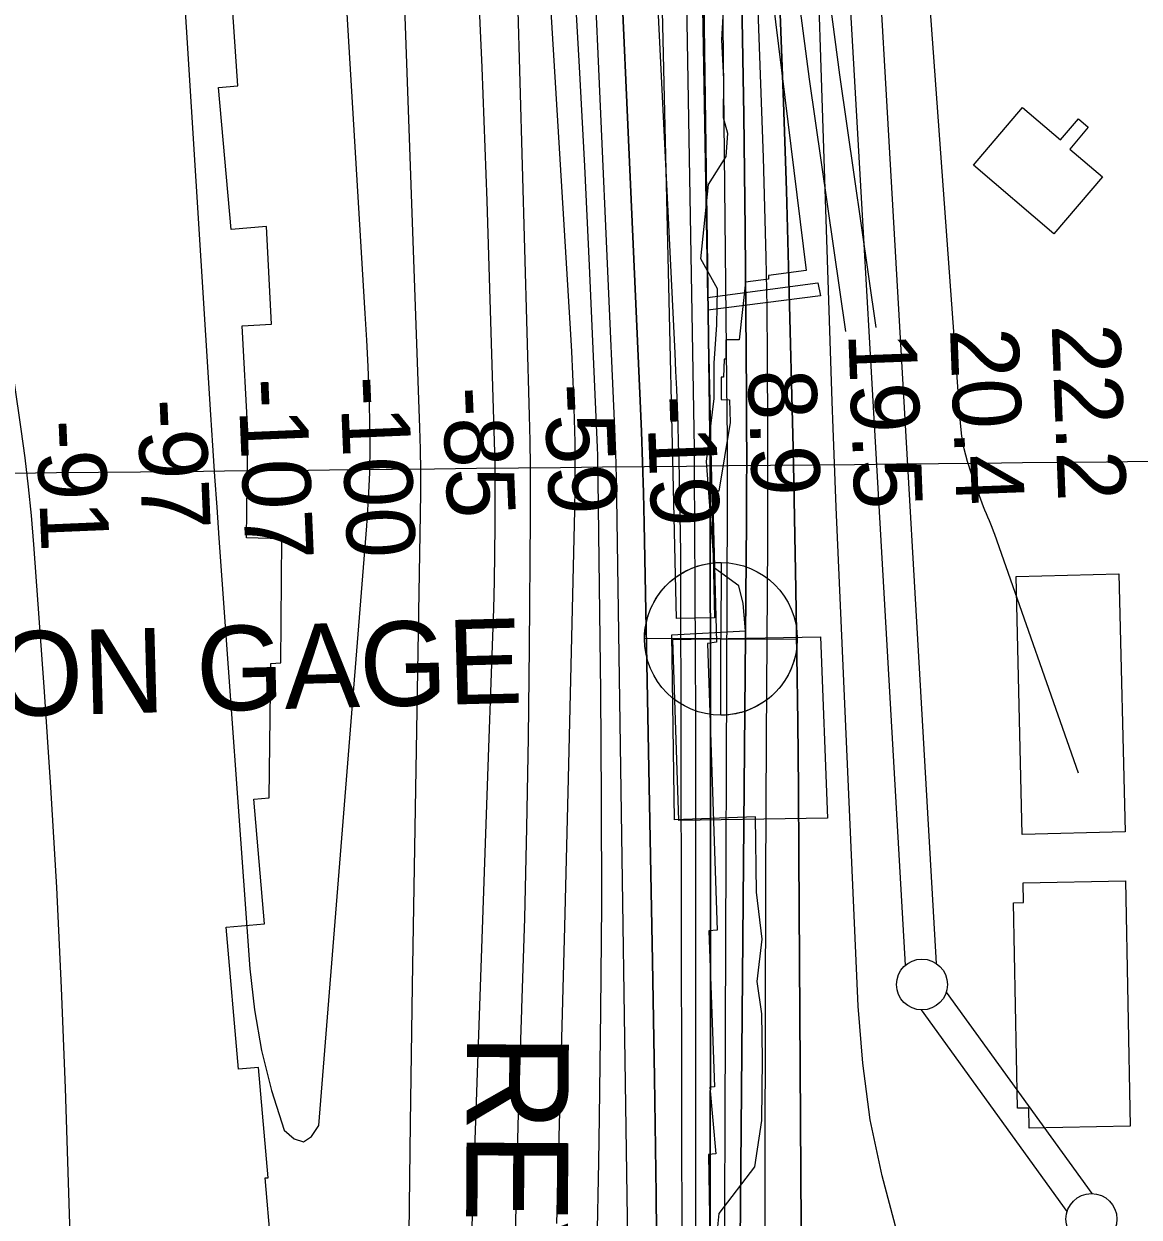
# Model space of a CAD drawing. Extents: x 3651524 to 3689615, y 505651 to 531377.
# Drawn here: x 3659567 to 3660662, y 522494 to 523666 of the extents above; entities that cross this region are included whole.
import ezdxf

# ---------------------------------------------------------------- set-up
doc = ezdxf.new("R2010")
doc.units = 0
for name, color, linetype in [('V-BLDG-OTLN', 7, 'Continuous'), ('V-CHAN-DOCK', 7, 'Continuous'), ('V-GRID-MAJR', 7, 'Continuous'), ('V-RIVR-EDGE', 7, 'Continuous'), ('V-RIVR-GAGE', 7, 'Continuous'), ('V-RIVR-GAGE-IDEN', 7, 'Continuous'), ('V-RIVR-RANG', 7, 'Continuous'), ('V-ROAD-CNTR', 7, 'Continuous'), ('V-RRAP-RVMT', 7, 'Continuous'), ('V-RRAP-RVMT-IDEN', 7, 'Continuous'), ('V-SURV-LINE', 7, 'Continuous'), ('V-TOPO-DPTH', 7, 'Continuous'), ('V-TOPO-MAJR', 7, 'Continuous'), ('V-TOPO-MINR', 7, 'Continuous'), ('V-TOPO-WATR', 7, 'Continuous')]:
    doc.layers.add(name, color=color, linetype=linetype)

msp = doc.modelspace()

# ---------------------------------------------------------------- linework, layer by layer
at = {"layer": 'V-BLDG-OTLN'}
for points in [[(3660499.185, 523526.95), (3660547.415, 523583.372), (3660584.617, 523551.569), (3660602.316, 523572.272), (3660612.052, 523563.947), (3660593.831, 523542.631), (3660625.819, 523515.286), (3660578.107, 523459.481)], [(3660547.2, 522869.505), (3660541.05, 523122.922), (3660642.023, 523125.374), (3660648.173, 522871.956)], [(3660648.548, 522824.021), (3660653.145, 522583.031), (3660553.914, 522581.134), (3660553.539, 522600.857), (3660542.416, 522600.646), (3660538.564, 522802.521), (3660548.349, 522802.707), (3660547.981, 522822.102)]]:
    msp.add_lwpolyline(points, close=True, dxfattribs=at)
at = {"layer": 'V-CHAN-DOCK'}
for points in [[(3660349.073, 523398.565), (3660238.38, 523384.489), (3660244.914, 523082.139), (3660207.497, 523081.612), (3660186.068, 524019.57), (3660225.288, 524021.251), (3660228.491, 523900.065), (3660307.638, 523909.948), (3660308.615, 523898.056), (3660229.488, 523889.36), (3660238.008, 523396.965), (3660346.324, 523411.082), (3660349.073, 523398.565)], [(3660356.036, 522885.416), (3660209.928, 522883.247), (3660204.16, 523060.891), (3660349.091, 523063.674), (3660356.036, 522885.416)]]:
    msp.add_lwpolyline(points, dxfattribs=at)
at = {"layer": 'V-GRID-MAJR'}
msp.add_spline([(3655639.78, 523183.706), (3660918.553, 523238.605), (3666197.317, 523294.271), (3671476.073, 523350.705), (3676754.821, 523407.907), (3682033.561, 523465.877), (3687312.292, 523524.615)], degree=3, dxfattribs=at)
at = {"layer": 'V-RIVR-EDGE'}
msp.add_lwpolyline([(3660246.867, 522470.971), (3660249.383, 522497.312), (3660284.422, 522543.18), (3660291.274, 522588.505), (3660292.037, 522649.163), (3660291.533, 522693.28), (3660286.71, 522725.154), (3660291.715, 522766.807), (3660286.314, 522812.775), (3660285.272, 522886.918), (3660205.611, 522884.051), (3660202.996, 523065.425), (3660275.307, 523069.535), (3660272.923, 523096.501), (3660268.677, 523113.668), (3660244.823, 523130.883), (3660237.116, 523235.678), (3660244.622, 523297.545), (3660244.709, 523332.47), (3660247.252, 523369.841), (3660247.952, 523405.377), (3660231.482, 523434.829), (3660239.015, 523507.724), (3660256.239, 523535.255), (3660258.133, 523557.921), (3660253.882, 523573.25), (3660253.976, 523611.238), (3660252.233, 523649.844), (3660254.156, 523684.152)], dxfattribs=at)
at = {"layer": 'V-RIVR-GAGE'}
for points in [[(3660251.372, 523136.632), (3660251.187, 523061.632), (3660176.187, 523061.817), (3660176.222, 523063.921), (3660176.344, 523066.494), (3660176.599, 523069.484), (3660176.97, 523072.441), (3660177.426, 523075.21), (3660178.036, 523078.188), (3660178.669, 523080.767), (3660179.337, 523083.139), (3660180.102, 523085.546), (3660181.078, 523088.277), (3660182.015, 523090.62), (3660183.026, 523092.922), (3660184.228, 523095.418), (3660185.664, 523098.124), (3660187.016, 523100.454), (3660188.419, 523102.683), (3660190.831, 523106.152), (3660192.531, 523108.37), (3660194.759, 523111.037), (3660196.909, 523113.39), (3660198.751, 523115.255), (3660201.525, 523117.834), (3660203.868, 523119.821), (3660206.33, 523121.739), (3660209.448, 523123.943), (3660211.827, 523125.474), (3660214.418, 523127.001), (3660217.397, 523128.59), (3660220.038, 523129.858), (3660222.632, 523130.984), (3660226.267, 523132.371), (3660229.51, 523133.432), (3660232.686, 523134.315), (3660235.942, 523135.066), (3660239.344, 523135.691), (3660243.397, 523136.226), (3660246.387, 523136.478), (3660248.933, 523136.598)], [(3660251.001, 522986.632), (3660251.187, 523061.632), (3660326.186, 523061.446), (3660326.133, 523058.791), (3660325.946, 523055.632), (3660325.694, 523053.041), (3660325.346, 523050.438), (3660324.808, 523047.313), (3660324.16, 523044.315), (3660323.292, 523040.996), (3660322.644, 523038.852), (3660321.671, 523036), (3660320.542, 523033.088), (3660319.442, 523030.547), (3660318.252, 523028.058), (3660316.969, 523025.608), (3660315.622, 523023.251), (3660313.978, 523020.617), (3660312.477, 523018.405), (3660310.353, 523015.541), (3660308.21, 523012.915), (3660305.578, 523009.993), (3660303.282, 523007.678), (3660300.793, 523005.38), (3660298.609, 523003.526), (3660296.966, 523002.224), (3660294.31, 523000.269), (3660292.396, 522998.968), (3660289.876, 522997.381), (3660287.212, 522995.851), (3660284.492, 522994.432), (3660282.368, 522993.421), (3660280.097, 522992.428), (3660277.48, 522991.392), (3660274.769, 522990.435), (3660271.493, 522989.433), (3660268.332, 522988.618), (3660265.902, 522988.089), (3660263.146, 522987.591), (3660260.759, 522987.245), (3660257.97, 522986.939), (3660255.774, 522986.772), (3660253.203, 522986.659)]]:
    msp.add_lwpolyline(points, close=True, dxfattribs=at)
msp.add_circle((3660251.187, 523061.632), 75, dxfattribs=at)
at = {"layer": 'V-ROAD-CNTR'}
for points in [[(3660403.73, 523367.378), (3660368.074, 523615.406), (3660346.877, 523777.012), (3660336.94, 523901.565), (3660333.341, 523955.329), (3660348.907, 524360.899), (3660351.762, 524756.645), (3660356.59, 524937.749), (3660437.61, 525023.281)], [(3660374.001, 523363.346), (3660338.353, 523611.321), (3660317.033, 523773.866), (3660307.02, 523899.37), (3660303.302, 523954.901), (3660314.174, 524238.169)]]:
    msp.add_lwpolyline(points, dxfattribs=at)
at = {"layer": 'V-RRAP-RVMT'}
for p, q in [((3660276.057, 523900.574), (3660334.975, 523423.42)), ((3659776.938, 523604.624), (3659770.445, 523697.82)), ((3659757.953, 523603.024), (3659776.938, 523604.624)), ((3659770.093, 523463.556), (3659757.953, 523603.024)), ((3659804.866, 523466.556), (3659770.093, 523463.556)), ((3659809.762, 523370.661), (3659804.866, 523466.556)), ((3660334.975, 523423.42), (3660297.909, 523418.323)), ((3660275.253, 523411.785), (3660269.018, 523355.39)), ((3660297.986, 523414.735), (3660275.253, 523411.785)), ((3660297.909, 523418.323), (3660297.986, 523414.735)), ((3659780.985, 523369.161), (3659809.762, 523370.661)), ((3659786.457, 523265.619), (3659780.985, 523369.161)), ((3660255.98, 523355.177), (3660255.912, 523336.375)), ((3660269.018, 523355.39), (3660255.98, 523355.177)), ((3660254.322, 523336.189), (3660253.762, 523318.56)), ((3660255.912, 523336.375), (3660254.322, 523336.189)), ((3660251.416, 523318.528), (3660251.393, 523296.645)), ((3660253.762, 523318.56), (3660251.416, 523318.528)), ((3660251.393, 523296.645), (3660259.776, 523296.266)), ((3660259.776, 523296.266), (3660260.158, 523273.981)), ((3660260.158, 523273.981), (3660249.156, 523206.79)), ((3659785.469, 523160.796), (3659786.457, 523265.619)), ((3660249.156, 523206.79), (3660242.94, 523206.6)), ((3660242.94, 523206.6), (3660246.991, 523058.508)), ((3659819.864, 523159.894), (3659785.469, 523160.796)), ((3659819.1, 523038.12), (3659819.864, 523159.894)), ((3660246.991, 523058.508), (3660237.917, 523057.026)), ((3660237.917, 523057.026), (3660247.481, 522775.556)), ((3659807.571, 522905.41), (3659809.257, 523037.468)), ((3659809.257, 523037.468), (3659819.1, 523038.12)), ((3659792.521, 522904.101), (3659807.571, 522905.41)), ((3659803.113, 522781.814), (3659792.521, 522904.101)), ((3659765.245, 522778.414), (3659803.113, 522781.814)), ((3659777.386, 522639.004), (3659765.245, 522778.414)), ((3660247.481, 522775.556), (3660239.319, 522775.047)), ((3660239.319, 522775.047), (3660244.772, 522621.622)), ((3659797.169, 522640.754), (3659777.386, 522639.004)), ((3659806.588, 522532.454), (3659797.169, 522640.754)), ((3660244.772, 522621.622), (3660240.476, 522621.314)), ((3660240.476, 522621.314), (3660246.141, 522555.877)), ((3660246.141, 522555.877), (3660239.124, 522555.264)), ((3660239.124, 522555.264), (3660240.322, 522474.722)), ((3659803.615, 522532.204), (3659806.588, 522532.454)), ((3659814.528, 522406.771), (3659803.615, 522532.204))]:
    msp.add_line(p, q, dxfattribs=at)
at = {"layer": 'V-SURV-LINE'}
for points in [[(3660386.448, 524067.969), (3660462.538, 522742.955)], [(3660432.586, 522741.256), (3660356.496, 524066.27)], [(3660472.563, 522714.753), (3660615.577, 522516.868)], [(3660591.268, 522499.288), (3660448.254, 522697.172)]]:
    msp.add_lwpolyline(points, dxfattribs=at)
for centre in [(3660448.708, 522722.152), (3660615.123, 522491.888)]:
    msp.add_circle(centre, 25, dxfattribs=at)
at = {"layer": 'V-TOPO-DPTH'}
for points in [[(3660211.802, 521616.591), (3660212.444, 521726.88), (3660212.987, 521837.171), (3660213.746, 522016.055), (3660213.815, 522036.903), (3660213.859, 522057.752), (3660213.863, 522078.601), (3660213.842, 522099.449), (3660211.829, 523128.812), (3660211.746, 523146.783), (3660211.599, 523164.754), (3660211.355, 523182.724), (3660211.047, 523200.693), (3660211.032, 523201.451), (3660210.646, 523219.04), (3660210.21, 523236.627), (3660209.699, 523254.213), (3660209.139, 523271.797), (3660208.5, 523289.379), (3660207.808, 523306.958), (3660207.036, 523324.534), (3660206.209, 523342.108), (3660158.102, 524317.479)], [(3660211.802, 521616.591), (3660212.444, 521726.88), (3660212.987, 521837.171), (3660213.746, 522016.055), (3660213.815, 522036.903), (3660213.859, 522057.752), (3660213.863, 522078.601), (3660213.842, 522099.449), (3660211.829, 523128.812), (3660211.746, 523146.783), (3660211.599, 523164.754), (3660211.355, 523182.724), (3660211.047, 523200.693), (3660211.032, 523201.451), (3660210.646, 523219.04), (3660210.21, 523236.627), (3660209.699, 523254.213), (3660209.139, 523271.797), (3660208.5, 523289.379), (3660207.808, 523306.958), (3660207.036, 523324.534), (3660206.209, 523342.108), (3660158.102, 524317.479)], [(3660228.583, 524108.955), (3660240.247, 523264.138), (3660240.404, 523250.988), (3660240.528, 523237.839), (3660240.603, 523224.689), (3660240.645, 523211.539), (3660240.979, 522962.568), (3660241.071, 522824.932), (3660241.041, 522687.297), (3660240.826, 522549.662), (3660240.489, 522412.026), (3660239.595, 522125.275), (3660239.479, 522091.694), (3660239.348, 522058.113), (3660239.195, 522024.533), (3660239.026, 521990.952), (3660236.656, 521547.642)], [(3660236.656, 521547.642), (3660239.026, 521990.952), (3660239.195, 522024.533), (3660239.348, 522058.113), (3660239.479, 522091.694), (3660239.595, 522125.275), (3660240.489, 522412.026), (3660240.826, 522549.662), (3660241.041, 522687.297), (3660241.071, 522824.932), (3660240.979, 522962.568), (3660240.645, 523211.539), (3660240.603, 523224.689), (3660240.528, 523237.839), (3660240.404, 523250.988), (3660240.247, 523264.138), (3660228.583, 524108.955)], [(3660142.159, 523962.069), (3660171.98, 523295.464), (3660173.213, 523265.333), (3660174.294, 523235.198), (3660175.145, 523205.056), (3660175.844, 523174.908), (3660184.165, 522745.258), (3660186.081, 522630.627), (3660187.591, 522515.991), (3660188.492, 522401.349), (3660188.988, 522286.702), (3660189.341, 522074.544), (3660189.347, 522065.974), (3660189.343, 522057.403), (3660189.324, 522048.833), (3660189.294, 522040.262), (3660188.968, 521966.904), (3660188.735, 521921.655), (3660188.457, 521876.406), (3660188.114, 521831.158), (3660187.726, 521785.909), (3660180.444, 521002.622)], [(3660142.159, 523962.069), (3660171.98, 523295.464), (3660173.213, 523265.333), (3660174.294, 523235.198), (3660175.145, 523205.056), (3660175.844, 523174.908), (3660184.165, 522745.258), (3660186.081, 522630.627), (3660187.591, 522515.991), (3660188.492, 522401.349), (3660188.988, 522286.702), (3660189.341, 522074.544), (3660189.347, 522065.974), (3660189.343, 522057.403), (3660189.324, 522048.833), (3660189.294, 522040.262), (3660188.968, 521966.904), (3660188.735, 521921.655), (3660188.457, 521876.406), (3660188.114, 521831.158), (3660187.726, 521785.909), (3660180.444, 521002.622)], [(3660153.012, 521270.884), (3660160.238, 522044.457), (3660160.306, 522050.41), (3660160.388, 522056.363), (3660160.494, 522062.316), (3660160.615, 522068.268), (3660161.2, 522094.568), (3660161.593, 522113.671), (3660161.942, 522132.774), (3660162.227, 522151.879), (3660162.468, 522170.984), (3660162.638, 522186.508), (3660162.828, 522213.376), (3660162.881, 522240.243), (3660162.727, 522267.11), (3660162.434, 522293.977), (3660149.09, 523199.972), (3660148.762, 523217.069), (3660148.334, 523234.164), (3660147.754, 523251.254), (3660147.073, 523268.341), (3660119.703, 523886.484)], [(3660153.012, 521270.884), (3660160.238, 522044.457), (3660160.306, 522050.41), (3660160.388, 522056.363), (3660160.494, 522062.316), (3660160.615, 522068.268), (3660161.2, 522094.568), (3660161.593, 522113.671), (3660161.942, 522132.774), (3660162.227, 522151.879), (3660162.468, 522170.984), (3660162.638, 522186.508), (3660162.828, 522213.376), (3660162.881, 522240.243), (3660162.727, 522267.11), (3660162.434, 522293.977), (3660149.09, 523199.972), (3660148.762, 523217.069), (3660148.334, 523234.164), (3660147.754, 523251.254), (3660147.073, 523268.341), (3660119.703, 523886.484)], [(3660271.866, 523688.051), (3660273.826, 523575.875), (3660275.141, 523463.686), (3660276.339, 523301.804), (3660276.495, 523270.545), (3660276.549, 523239.285), (3660276.452, 523208.025), (3660276.255, 523176.765), (3660267.782, 522208.587), (3660267.561, 522183.572), (3660267.337, 522158.557), (3660267.11, 522133.542), (3660266.879, 522108.527), (3660266.468, 522064.344), (3660266.441, 522061.42), (3660266.416, 522058.497), (3660266.393, 522055.574), (3660266.37, 522052.65), (3660259.75, 521154.194)], [(3660259.75, 521154.194), (3660266.37, 522052.65), (3660266.393, 522055.574), (3660266.416, 522058.497), (3660266.441, 522061.42), (3660266.468, 522064.344), (3660266.879, 522108.527), (3660267.11, 522133.542), (3660267.337, 522158.557), (3660267.561, 522183.572), (3660267.782, 522208.587), (3660276.255, 523176.765), (3660276.452, 523208.025), (3660276.549, 523239.285), (3660276.495, 523270.545), (3660276.339, 523301.804), (3660275.141, 523463.686), (3660273.826, 523575.875), (3660271.866, 523688.051)], [(3660309.51, 523675.548), (3660312.752, 523588.682), (3660315.51, 523501.8), (3660317.944, 523414.906), (3660322.125, 523249.186), (3660322.223, 523245.144), (3660322.315, 523241.102), (3660322.399, 523237.06), (3660322.476, 523233.018), (3660324.702, 523110.507), (3660325.771, 523045.208), (3660326.684, 522979.908), (3660327.361, 522914.604), (3660327.883, 522849.298), (3660332.384, 522121.58), (3660332.507, 522091.306), (3660332.543, 522061.033), (3660332.45, 522030.759), (3660332.271, 522000.486), (3660329.688, 521679.827), (3660328.437, 521562.401)]]:
    msp.add_lwpolyline(points, dxfattribs=at)
at = {"layer": 'V-TOPO-MAJR'}
for points in [[(3659716.655, 523813.725), (3659750.092, 523281.62), (3659752.036, 523251.342), (3659754.034, 523221.068), (3659756.113, 523190.799), (3659758.246, 523160.535), (3659788.634, 522737.546), (3659793.221, 522697.154), (3659799.987, 522657.224), (3659810.021, 522617.987), (3659822.233, 522579.213), (3659832.093, 522570.691), (3659841.212, 522567.695), (3659849.218, 522572.989), (3659856.482, 522583.808), (3659903.523, 523172.762), (3659905.191, 523198.761), (3659906.317, 523224.774), (3659906.631, 523250.811), (3659906.402, 523276.862), (3659905.626, 523302.919), (3659904.666, 523328.968), (3659903.427, 523355.005), (3659902.003, 523381.035), (3659845.319, 524324.679)], [(3660129.686, 522465.554), (3660131.231, 522547.943), (3660132.002, 522591.917), (3660133.374, 522696.297), (3660134.134, 522800.679), (3660133.978, 522905.063), (3660133.21, 523009.449), (3660130.768, 523217.274), (3660130.635, 523225.363), (3660130.45, 523233.45), (3660130.188, 523241.536), (3660129.874, 523249.62), (3660122.084, 523428.422), (3660117.508, 523525.888), (3660112.494, 523623.331), (3660106.824, 523720.737)]]:
    msp.add_lwpolyline(points, dxfattribs=at)
at = {"layer": 'V-TOPO-MINR'}
for points in [[(3660453.124, 522384.898), (3660423.959, 522480.021), (3660409.533, 522534.4), (3660397.915, 522589.264), (3660390.51, 522644.852), (3660385.913, 522700.925), (3660364.544, 523190.816), (3660363.454, 523216.759), (3660362.419, 523242.703), (3660361.468, 523268.651), (3660360.572, 523294.601), (3660336.683, 524020.527), (3660334.835, 524077.811), (3660333.038, 524135.097), (3660331.316, 524192.385), (3660329.644, 524249.674), (3660328.817, 524278.653), (3660327.721, 524321.457), (3660326.792, 524364.263), (3660326.111, 524407.075), (3660325.598, 524449.889), (3660316.37, 525466.02)], [(3660090.061, 522487.547), (3660094.16, 522633.15), (3660097.942, 522778.761), (3660101.514, 522924.378), (3660107.695, 523188.044), (3660108.048, 523210.313), (3660108.177, 523232.583), (3660107.969, 523254.851), (3660107.537, 523277.119), (3660106.822, 523299.382), (3660105.957, 523321.639), (3660104.864, 523343.885), (3660103.621, 523366.124), (3660044.887, 524328.51)], [(3660211.802, 521616.591), (3660212.444, 521726.88), (3660212.987, 521837.171), (3660213.746, 522016.055), (3660213.815, 522036.903), (3660213.859, 522057.752), (3660213.863, 522078.601), (3660213.842, 522099.449), (3660211.829, 523128.812), (3660211.746, 523146.783), (3660211.599, 523164.754), (3660211.355, 523182.724), (3660211.047, 523200.693), (3660211.032, 523201.451), (3660210.646, 523219.04), (3660210.21, 523236.627), (3660209.699, 523254.213), (3660209.139, 523271.797), (3660208.5, 523289.379), (3660207.808, 523306.958), (3660207.036, 523324.534), (3660206.209, 523342.108), (3660158.102, 524317.479)], [(3660294.548, 522412.756), (3660294.697, 522550.65), (3660294.987, 522688.544), (3660295.488, 522826.438), (3660296.129, 522964.331), (3660297.172, 523156.758), (3660297.326, 523198.437), (3660297.383, 523240.116), (3660297.298, 523281.795), (3660297.116, 523323.474), (3660297.026, 523338.209), (3660296.507, 523387.251), (3660295.693, 523436.287), (3660294.437, 523485.313), (3660292.888, 523534.333), (3660264.783, 524312.277)], [(3660602.53, 522929.57), (3660520.354, 523163.994), (3660519.088, 523167.453), (3660517.761, 523170.888), (3660516.341, 523174.285), (3660514.859, 523177.657), (3660513.368, 523181.027), (3660511.926, 523184.416), (3660510.559, 523187.836), (3660509.241, 523191.277), (3660497.285, 523223.545), (3660493.343, 523235.751), (3660490.107, 523248.11), (3660487.93, 523260.699), (3660486.458, 523273.441), (3660414.629, 524262.457)], [(3659965.176, 521570.556), (3659958.707, 521692.115), (3659942.003, 522012.958), (3659941.316, 522029.038), (3659940.831, 522045.123), (3659940.647, 522061.214), (3659940.665, 522077.309), (3659943.154, 522315.505), (3659944.703, 522450.699), (3659946.435, 522585.89), (3659948.44, 522721.078), (3659950.627, 522856.263), (3659956.263, 523184.074), (3659956.459, 523205.297), (3659956.431, 523226.519), (3659956.067, 523247.737), (3659955.478, 523268.953), (3659921.065, 524232.887)], [(3660236.656, 521547.642), (3660239.026, 521990.952), (3660239.195, 522024.533), (3660239.348, 522058.113), (3660239.479, 522091.694), (3660239.595, 522125.275), (3660240.489, 522412.026), (3660240.826, 522549.662), (3660241.041, 522687.297), (3660241.071, 522824.932), (3660240.979, 522962.568), (3660240.645, 523211.539), (3660240.603, 523224.689), (3660240.528, 523237.839), (3660240.404, 523250.988), (3660240.247, 523264.138), (3660228.583, 524108.955)], [(3660180.444, 521002.622), (3660187.726, 521785.909), (3660188.114, 521831.158), (3660188.457, 521876.406), (3660188.735, 521921.655), (3660188.968, 521966.904), (3660189.294, 522040.262), (3660189.324, 522048.833), (3660189.343, 522057.403), (3660189.347, 522065.974), (3660189.341, 522074.544), (3660188.988, 522286.702), (3660188.492, 522401.349), (3660187.591, 522515.991), (3660186.081, 522630.627), (3660184.165, 522745.258), (3660175.844, 523174.908), (3660175.145, 523205.056), (3660174.294, 523235.198), (3660173.213, 523265.333), (3660171.98, 523295.464), (3660142.159, 523962.069)], [(3660153.012, 521270.884), (3660160.238, 522044.457), (3660160.306, 522050.41), (3660160.388, 522056.363), (3660160.494, 522062.316), (3660160.615, 522068.268), (3660161.2, 522094.568), (3660161.593, 522113.671), (3660161.942, 522132.774), (3660162.227, 522151.879), (3660162.468, 522170.984), (3660162.638, 522186.508), (3660162.828, 522213.376), (3660162.881, 522240.243), (3660162.727, 522267.11), (3660162.434, 522293.977), (3660149.09, 523199.972), (3660148.762, 523217.069), (3660148.334, 523234.164), (3660147.754, 523251.254), (3660147.073, 523268.341), (3660119.703, 523886.484)], [(3660063.553, 521536.722), (3660044.55, 522020.283), (3660044.093, 522034.79), (3660043.788, 522049.299), (3660043.708, 522063.811), (3660043.779, 522078.325), (3660047.112, 522340.677), (3660048.549, 522429.907), (3660050.39, 522519.127), (3660052.838, 522608.332), (3660055.691, 522697.528), (3660055.727, 522698.551), (3660058.494, 522787.236), (3660060.768, 522875.931), (3660062.301, 522964.643), (3660063.34, 523053.364), (3660064.299, 523180.598), (3660064.355, 523205.71), (3660064.233, 523230.82), (3660063.845, 523255.927), (3660063.279, 523281.032), (3660047.317, 523854.152)], [(3660224.355, 521615.026), (3660225.028, 521743.768), (3660226.238, 522003.665), (3660226.346, 522030.797), (3660226.431, 522057.93), (3660226.479, 522085.063), (3660226.504, 522112.197), (3660226.682, 522858.814), (3660226.643, 522921.884), (3660226.533, 522984.953), (3660226.315, 523048.022), (3660226.024, 523111.092), (3660225.397, 523226.214), (3660225.357, 523231.722), (3660225.305, 523237.229), (3660225.234, 523242.736), (3660225.15, 523248.243), (3660216.105, 523781.628)], [(3659994.558, 522127.891), (3660023.378, 522955.038), (3660024.337, 522982.249), (3660025.312, 523009.459), (3660026.31, 523036.668), (3660027.322, 523063.876), (3660028.203, 523091.087), (3660028.894, 523118.302), (3660029.3, 523145.522), (3660029.515, 523172.747), (3660029.626, 523214.238), (3660029.607, 523221.831), (3660029.538, 523229.424), (3660029.392, 523237.016), (3660029.194, 523244.607), (3660021.514, 523491.641), (3660016.668, 523622.71), (3660010.799, 523753.726)], [(3660248.241, 521351.097), (3660252.141, 521977.884), (3660252.39, 522018.093), (3660252.638, 522058.302), (3660252.885, 522098.51), (3660253.131, 522138.719), (3660253.724, 522235.931), (3660254.233, 522324.746), (3660254.701, 522413.561), (3660255.106, 522502.376), (3660255.468, 522591.192), (3660257.717, 523194.946), (3660257.751, 523216.737), (3660257.724, 523238.528), (3660257.603, 523260.319), (3660257.419, 523282.11), (3660252.703, 523729.254)], [(3659490.687, 523672.21), (3659501.281, 523640.502), (3659510.522, 523608.449), (3659517.735, 523575.88), (3659523.595, 523542.966), (3659563.728, 523267.686), (3659567.543, 523239.389), (3659570.951, 523211.048), (3659573.749, 523182.64), (3659576.14, 523154.188), (3659586.374, 523014.385), (3659592.969, 522915.966), (3659598.754, 522817.504), (3659603.324, 522718.979), (3659607.084, 522620.411), (3659624.186, 522085.419), (3659624.855, 522058.883), (3659625.285, 522032.345), (3659625.357, 522005.803), (3659625.19, 521979.259), (3659622.526, 521775.165), (3659619.966, 521646.604)], [(3660328.437, 521562.401), (3660329.688, 521679.827), (3660332.271, 522000.486), (3660332.45, 522030.759), (3660332.543, 522061.033), (3660332.507, 522091.306), (3660332.384, 522121.58), (3660327.883, 522849.298), (3660327.361, 522914.604), (3660326.684, 522979.908), (3660325.771, 523045.208), (3660324.702, 523110.507), (3660322.476, 523233.018), (3660322.399, 523237.06), (3660322.315, 523241.102), (3660322.223, 523245.144), (3660322.125, 523249.186), (3660317.944, 523414.906), (3660315.51, 523501.8), (3660312.752, 523588.682), (3660309.51, 523675.548)]]:
    msp.add_lwpolyline(points, dxfattribs=at)
at = {"layer": 'V-TOPO-WATR'}
msp.add_lwpolyline([(3660259.75, 521154.194), (3660266.37, 522052.65), (3660266.393, 522055.574), (3660266.416, 522058.497), (3660266.441, 522061.42), (3660266.468, 522064.344), (3660266.879, 522108.527), (3660267.11, 522133.542), (3660267.337, 522158.557), (3660267.561, 522183.572), (3660267.782, 522208.587), (3660276.255, 523176.765), (3660276.452, 523208.025), (3660276.549, 523239.285), (3660276.495, 523270.545), (3660276.339, 523301.804), (3660275.141, 523463.686), (3660273.826, 523575.875), (3660271.866, 523688.051)], dxfattribs=at)

# ---------------------------------------------------------------- texts
at = {"layer": 'V-RIVR-GAGE-IDEN'}
msp.add_text('CARROLLTON GAGE', height=83, rotation=1.52077, dxfattribs=at).set_placement((3658947.75, 522969.509))
at = {"layer": 'V-RIVR-RANG'}
for s, rotation, p in [('22.2', 272.148326, (3660576.084, 523370.102)), ('19.5', 272.148326, (3660376.243, 523362.128)), ('20.4', 272.148326, (3660476.164, 523366.115)), ('8.9', 272.148326, (3660277.559, 523325.191)), ('-107', 272.426694, (3659777.055, 523316.672)), ('-100', 272.426694, (3659877.054, 523318.814)), ('-85', 272.426694, (3659977.588, 523308.307)), ('-59', 272.426694, (3660077.543, 523311.504)), ('-97', 272.426694, (3659677.827, 523296.345)), ('-19', 272.148326, (3660178.439, 523299.853)), ('-91', 272.426694, (3659578.61, 523275.755))]:
    msp.add_text(s, height=67, rotation=rotation, dxfattribs=at).set_placement(p)
at = {"layer": 'V-RRAP-RVMT-IDEN'}
msp.add_text('REV.', height=99.9998, rotation=269.697003, dxfattribs=at).set_placement((3660001.958, 522674.442))

doc.saveas('drawing.dxf')
